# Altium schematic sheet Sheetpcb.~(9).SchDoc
size A; SheetNumber: 2; SheetTotal: 2
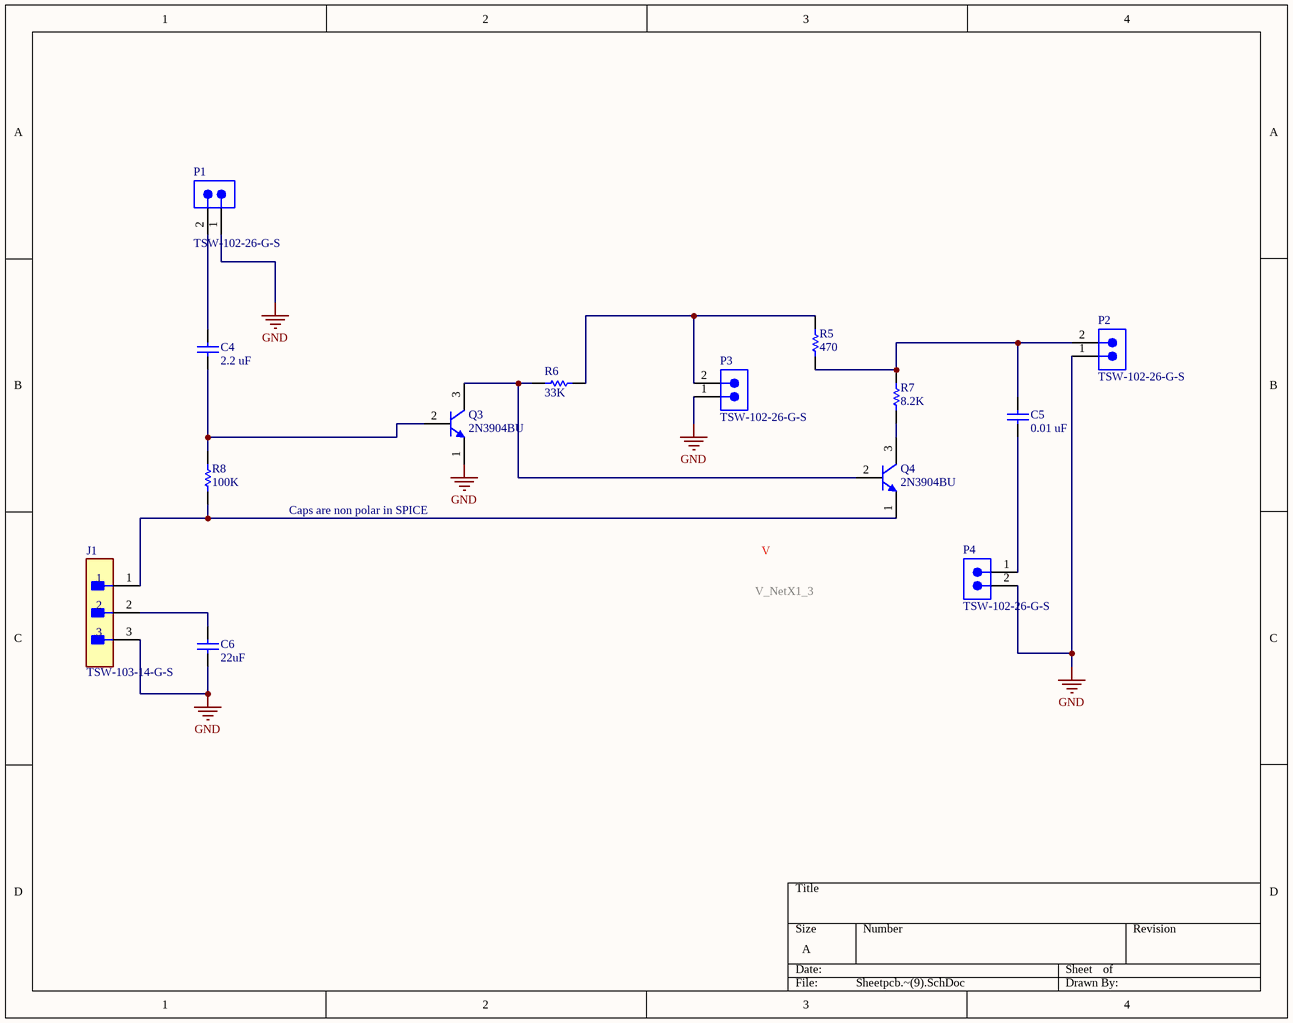
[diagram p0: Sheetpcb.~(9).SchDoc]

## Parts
C4  value 2.2 uF  (hidden comment: Capacitor)
C5  value 0.01 uF  (hidden comment: Capacitor)
C6  value 22uF  (hidden comment: Capacitor)
J1  TSW-103-14-G-S  [FP-TSW-103-14-G-S-MFG]
P1  TSW-102-26-G-S  [SMTC-TSW-102-26-XX-S]
P2  TSW-102-26-G-S  [SMTC-TSW-102-26-XX-S]
P3  TSW-102-26-G-S  [SMTC-TSW-102-26-XX-S]
P4  TSW-102-26-G-S  [SMTC-TSW-102-26-XX-S]
Q3  2N3904BU  [FAIR-TO-92]
Q4  2N3904BU  [FAIR-TO-92]
R5  value 470  (hidden comment: Resistor)
R6  value 33K  (hidden comment: Resistor)
R7  value 8.2K  (hidden comment: Resistor)
R8  value 100K  (hidden comment: Resistor)

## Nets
GND: C6.1 J1.3 P1.1 P2.1 P3.1 P4.2 Q3.1(E)
NetC4_1: C4.1 Q3.2(B) R8.2
NetC4_2: C4.2 P1.2
NetC5_1: C5.1 P4.1
NetC5_2: C5.2 P2.2 R5.1 R7.1
NetC6_2: C6.2 J1.2
NetJ1_1: J1.1 Q4.1(E) R8.1
NetP3_2: P3.2 R5.2 R6.1
NetQ3_3: Q3.3(C) Q4.2(B) R6.2
NetQ4_3: Q4.3(C) R7.2

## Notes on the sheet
- Caps are non polar in SPICE

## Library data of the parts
C4-C6 = Capacitor: SimulationGenericComponent: True
J1 = CMP-02766-001743-1: CONN HEADER VERT 3POS 2.54MM; Max Voltage Rating (AC): 550V; Number of Positions: 3; Max Current Rating: 7.6A; Gender: Male
P1-P4 = CMP-1024-00327-1: 0.025" SQ Post Header, Through-hole, Vertical, -55 to 125 degC, 2.54 mm Pitch, 2-Pin, Male, RoHS; Manufacturer: Samtec; Pitch: 2.54 mm
Q3 Q4 = CMP-2000-04944-1: NPN General-Purpose Amplifier, 40 V VCEO, 0.2 A, -55 to 150 degC, 2-Pin TO-92, RoHS, Bulk; Manufacturer: FairchildSemiconductor; Maximum Collector Base Voltage: 60V; Minimum DC Current Gain: 40@0.1mA@1V; Maximum Collector Emitter Voltage: 40V; Maximum DC Collector Current: 0.2A; Rad Hard: No; Maximum Operating Frequency: 300(Min)MHz; Maximum Collector Emitter Saturation Voltage: 0.2@1mA@10mA; Maximum Power Dissipation: 625mW
R5-R8 = Resistor: TC1: 0; SimulationGenericComponent: True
